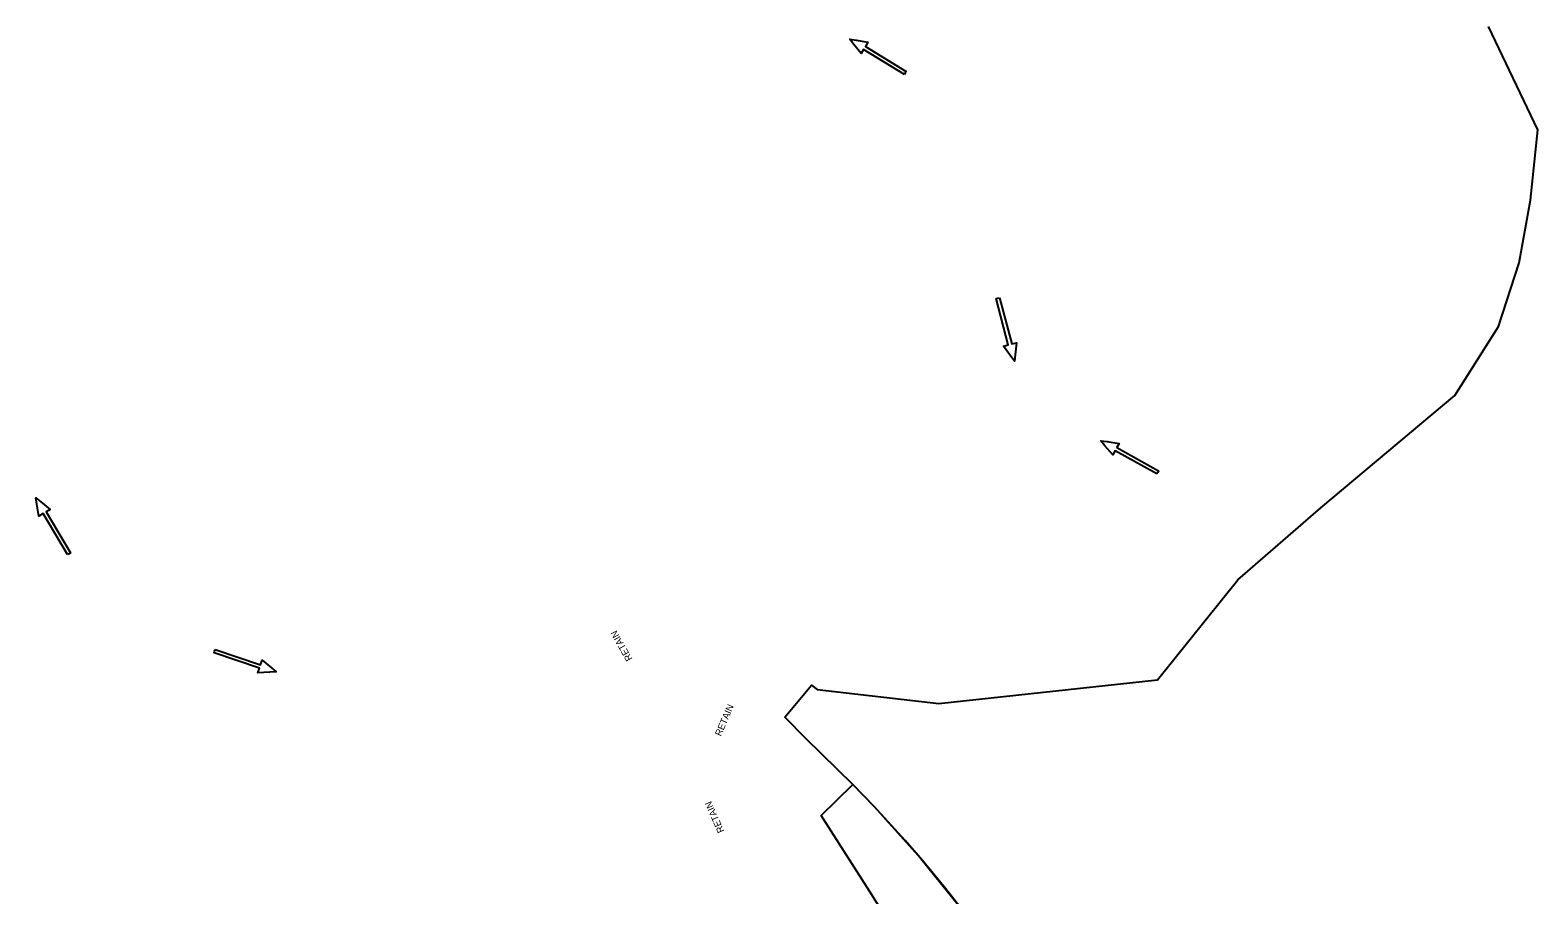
# Model space of a CAD drawing. Extents: x 465700 to 483515, y 488970 to 507540.
# Drawn here: x 476964 to 478073, y 499740 to 500375 of the extents above; entities that cross this region are included whole.
import ezdxf

# ---------------------------------------------------------------- set-up
doc = ezdxf.new("R2010")
doc.units = 0
for name, color, linetype in [('Default', 7, 'Continuous'), ('Exist Plan Preparation Drainage Flow Arrows', 7, 'Continuous'), ('Exist Plan Preparation Watershed Blue', 7, 'Continuous'), ('Prop Drainage Structure Pipe Collar Label', 7, 'Continuous')]:
    doc.layers.add(name, color=color, linetype=linetype)

# ---------------------------------------------------------------- blocks, each defined once
blk = doc.blocks.new('Existing ground flow arrow')
at = {"layer": 'Default'}
blk.add_line((2.5, -4.3), (2.5, -4.3), dxfattribs=at)
blk.add_lwpolyline([(-1.3, -47.2), (-1.3, -12.5), (-4.8, -12.5), (-1.7, -4.3), (0, 0), (1.7, -4.3), (4.8, -12.5), (1.3, -12.5), (1.3, -47.2), (0, -47.2)], close=True, dxfattribs=at)

msp = doc.modelspace()

# ---------------------------------------------------------------- linework, layer by layer
at = {"layer": 'Exist Plan Preparation Watershed Blue'}
for points in [[(477653.6, 499722.8), (477637, 499744.2), (477620.2, 499764.7), (477607.4, 499779.6), (477584.6, 499804.6), (477569, 499820.6), (477534.5, 499854.3), (477518.9, 499870.3), (477538.6, 499893.7), (477542.7, 499890.5), (477632.1, 499880.2), (477792.9, 499897.6), (477852, 499971.2), (477913, 500024.1), (478011.5, 500106.8), (478043.6, 500157.4), (478058.7, 500204.3), (478067.2, 500250.3), (478072.5, 500302), (478036.2, 500378.1)], [(477611, 499694.8), (477581.2, 499742.3), (477545.6, 499797.8), (477569, 499820.6), (477584.6, 499804.6), (477619, 499766.2), (477648.8, 499729.2)]]:
    msp.add_lwpolyline(points, dxfattribs=at)

# ---------------------------------------------------------------- block references
at = {"layer": 'Exist Plan Preparation Drainage Flow Arrows'}
for p, xscale, yscale, rotation in [((477566.7, 500368.9), 1.012407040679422, 1.0124070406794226, 58.594176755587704), ((477687.7, 500132.1), 1.0124070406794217, 1.0124070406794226, -165.2955171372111), ((477751.3, 500073.4), 1.0124070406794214, 1.0124070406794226, 60.972136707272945), ((476968.2, 500031.4), 1.0124070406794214, 1.0124070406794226, 30.84470458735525), ((477145, 499903.5), 1.012407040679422, 1.0124070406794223, -108.52785668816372)]:
    msp.add_blockref('Existing ground flow arrow', p, dxfattribs=dict(at, xscale=xscale, yscale=yscale, rotation=rotation))

# ---------------------------------------------------------------- texts
at = {"layer": 'Prop Drainage Structure Pipe Collar Label'}
for rotation, p in [(119.4242, (477407, 499913.1)), (66.6751, (477471.9, 499855.8)), (113.7794, (477474.5, 499786.4))]:
    msp.add_text('RETAIN', height=5, rotation=rotation, dxfattribs=at).set_placement(p)

doc.saveas('drawing.dxf')
